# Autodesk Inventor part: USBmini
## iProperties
Shininess: 64.0
Length Units: 11272
Angle Units: 11279
Time Units: 11290
Mass Units: 11286
Length Display Precision: 3
Angle Display Precision: 2
Compacted: True
Part Number: USBmini
Document SubType Name: Modeling
Created: 2007-10
Designer: jpalmisano
Manufacturer: Standard
Standards Organization: Custom
Density: 0.0
Volumn: 0.0
Area: 0.0
PropertySet Name: Model Information
Control State: 0
Master: False
Checked Out: False
Author: jpalmisano
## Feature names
1. Extrusion1
2. Extrusion2
3. Extrusion3
4. Fillet1
5. Fillet2
